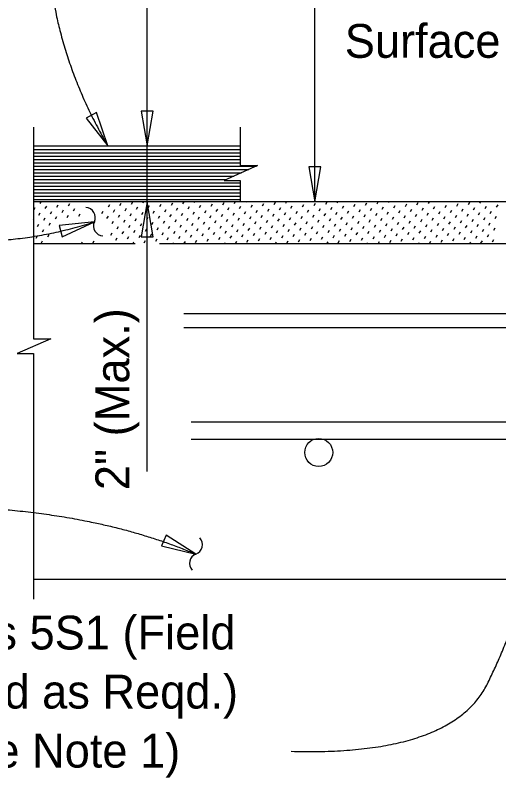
# Model space of a CAD drawing. Extents: x 120632.7 to 120668.8, y 120715.7 to 120740.6.
# Drawn here: x 120645.927 to 120647.369, y 120721.862 to 120724.135 of the extents above; entities that cross this region are included whole.
import ezdxf

# ---------------------------------------------------------------- set-up
doc = ezdxf.new("R2010")
doc.units = 0
for name, color, linetype in [('Dimension', 7, 'Continuous'), ('Miscellaneous', 7, 'Continuous'), ('Rebar_h', 7, 'Continuous'), ('TextStructures', 7, 'Continuous'), ('TrafBarrierConc', 7, 'Continuous')]:
    doc.layers.add(name, color=color, linetype=linetype)

msp = doc.modelspace()

# ---------------------------------------------------------------- linework, layer by layer
at = {"layer": 'Dimension'}
for p, q in [((120646.3205, 120722.7748), (120646.3205, 120726.2451)), ((120646.8205, 120723.5784), (120646.8205, 120726.2451))]:
    msp.add_line(p, q, dxfattribs=at)
for points in [[(120646.3205, 120723.7451), (120646.3382, 120723.8492), (120646.3029, 120723.8492)], [(120646.2035, 120723.7451), (120646.1695, 120723.845), (120646.1384, 120723.8282)], [(120646.8205, 120723.5784), (120646.8382, 120723.6826), (120646.8029, 120723.6826)], [(120646.3205, 120723.5784), (120646.3029, 120723.4743), (120646.3382, 120723.4743)], [(120646.1632, 120723.5191), (120646.0582, 120723.5084), (120646.0675, 120723.4744)], [(120646.4659, 120722.5283), (120646.3771, 120722.5855), (120646.3633, 120722.553)]]:
    msp.add_lwpolyline(points, close=True, dxfattribs=at)
for points in [[(120645.9811, 120723.8013), (120645.9811, 120723.1705), (120646.0328, 120723.1705), (120645.9328, 120723.1263), (120645.9811, 120723.1263), (120645.9811, 120722.3942)], [(120646.5983, 120723.8013), (120646.5983, 120723.6865), (120646.65, 120723.6865), (120646.55, 120723.6423), (120646.5983, 120723.6423), (120646.5983, 120723.5784)]]:
    msp.add_lwpolyline(points, dxfattribs=at)
for centre, start, end in [((120646.1361, 120723.5319), 335.1447, 86.8719), ((120646.1902, 120723.5069), 155.1447, 266.8719), ((120646.4554, 120722.5564), 291.0208, 42.748), ((120646.4768, 120722.5008), 111.0208, 222.748)]:
    msp.add_arc(centre, 0.0298, start, end, dxfattribs=at)
for points in [[(120645.8334, 120724.7826), (120646.0481, 120724.7906), (120646.0065, 120724.0831), (120646.2035, 120723.7451)], [(120645.7174, 120723.4648), (120645.9402, 120723.4472), (120646.1633, 120723.519)], [(120646.75, 120721.9408), (120647.2284, 120721.9277), (120647.4429, 120722.3562), (120647.6394, 120723.1429), (120647.8936, 120723.5), (120648.3041, 120723.1905)], [(120645.6303, 120722.6723), (120646.1265, 120722.6734), (120646.466, 120722.5283)]]:
    msp.add_open_spline(points, degree=2, dxfattribs=at)
at = {"layer": 'Miscellaneous'}
for p, q in [((120645.9812, 120723.7451), (120646.5984, 120723.7451)), ((120645.9812, 120723.7351), (120646.5984, 120723.7351)), ((120645.9812, 120723.7251), (120646.5984, 120723.7251)), ((120645.9812, 120723.7151), (120646.5984, 120723.7151)), ((120645.9812, 120723.7051), (120646.5984, 120723.7051)), ((120645.9812, 120723.6951), (120646.5984, 120723.6951)), ((120645.9812, 120723.6851), (120646.6469, 120723.6851)), ((120645.9812, 120723.6751), (120646.6243, 120723.6751)), ((120645.9812, 120723.6651), (120646.6016, 120723.6651)), ((120645.9812, 120723.6551), (120646.579, 120723.6551)), ((120645.9812, 120723.6451), (120646.5563, 120723.6451)), ((120645.9812, 120723.6351), (120646.5984, 120723.6351)), ((120645.9812, 120723.6251), (120646.5984, 120723.6251)), ((120645.9812, 120723.6151), (120646.5984, 120723.6151)), ((120645.9812, 120723.6051), (120646.5984, 120723.6051)), ((120645.9812, 120723.5951), (120646.5984, 120723.5951)), ((120645.9812, 120723.5851), (120646.5984, 120723.5851)), ((120647.6222, 120723.5784), (120645.9812, 120723.5784)), ((120646.0016, 120723.5738), (120646.0043, 120723.5784)), ((120646.0361, 120723.5778), (120646.0365, 120723.5784)), ((120646.2739, 120723.5716), (120646.2778, 120723.5784)), ((120646.3084, 120723.5757), (120646.31, 120723.5784)), ((120646.3928, 120723.5685), (120646.3968, 120723.5755)), ((120646.4273, 120723.5726), (120646.4307, 120723.5784)), ((120646.4619, 120723.5766), (120646.4629, 120723.5784)), ((120646.5462, 120723.5695), (120646.5503, 120723.5765)), ((120646.5808, 120723.5736), (120646.5836, 120723.5784)), ((120646.6153, 120723.5776), (120646.6158, 120723.5784)), ((120646.6996, 120723.5705), (120646.7037, 120723.5775)), ((120646.7342, 120723.5745), (120646.7364, 120723.5784)), ((120646.8531, 120723.5714), (120646.8571, 120723.5784)), ((120646.8876, 120723.5755), (120646.8893, 120723.5784)), ((120646.9719, 120723.5683), (120646.976, 120723.5753)), ((120647.0065, 120723.5724), (120647.01, 120723.5784)), ((120647.041, 120723.5764), (120647.0422, 120723.5784)), ((120647.1254, 120723.5693), (120647.1294, 120723.5763)), ((120647.1599, 120723.5733), (120647.1629, 120723.5784)), ((120647.1945, 120723.5774), (120647.1951, 120723.5784)), ((120647.2788, 120723.5702), (120647.2829, 120723.5772)), ((120647.3133, 120723.5743), (120647.3157, 120723.5784)), ((120647.3479, 120723.5783), (120647.3479, 120723.5784)), ((120645.9823, 120723.5545), (120645.9863, 120723.5615)), ((120646.0168, 120723.5585), (120646.0209, 120723.5655)), ((120646.0514, 120723.5626), (120646.0554, 120723.5696)), ((120646.0666, 120723.5473), (120646.0707, 120723.5543)), ((120646.0859, 120723.5666), (120646.09, 120723.5736)), ((120646.1012, 120723.5514), (120646.1052, 120723.5584)), ((120646.2048, 120723.5635), (120646.2089, 120723.5705)), ((120646.2201, 120723.5483), (120646.2241, 120723.5553)), ((120646.2394, 120723.5676), (120646.2434, 120723.5746)), ((120646.2546, 120723.5523), (120646.2587, 120723.5593)), ((120646.2891, 120723.5564), (120646.2932, 120723.5634)), ((120646.3237, 120723.5604), (120646.3277, 120723.5674)), ((120646.3389, 120723.5452), (120646.343, 120723.5522)), ((120646.3582, 120723.5645), (120646.3623, 120723.5715)), ((120646.3735, 120723.5492), (120646.3775, 120723.5562)), ((120646.408, 120723.5533), (120646.4121, 120723.5603)), ((120646.4426, 120723.5574), (120646.4466, 120723.5643)), ((120646.4771, 120723.5614), (120646.4812, 120723.5684)), ((120646.4924, 120723.5462), (120646.4964, 120723.5532)), ((120646.5117, 120723.5655), (120646.5157, 120723.5725)), ((120646.5269, 120723.5502), (120646.531, 120723.5572)), ((120646.5615, 120723.5543), (120646.5655, 120723.5613)), ((120646.596, 120723.5583), (120646.6001, 120723.5653)), ((120646.6305, 120723.5624), (120646.6346, 120723.5694)), ((120646.6458, 120723.5471), (120646.6498, 120723.5541)), ((120646.6651, 120723.5664), (120646.6691, 120723.5734)), ((120646.6803, 120723.5512), (120646.6844, 120723.5582)), ((120646.7149, 120723.5552), (120646.7189, 120723.5622)), ((120646.7494, 120723.5593), (120646.7535, 120723.5663)), ((120646.784, 120723.5633), (120646.788, 120723.5703)), ((120646.7992, 120723.5481), (120646.8033, 120723.5551)), ((120646.8185, 120723.5674), (120646.8226, 120723.5744)), ((120646.8338, 120723.5521), (120646.8378, 120723.5591)), ((120646.8683, 120723.5562), (120646.8724, 120723.5632)), ((120646.9029, 120723.5602), (120646.9069, 120723.5672)), ((120646.9181, 120723.545), (120646.9222, 120723.552)), ((120646.9374, 120723.5643), (120646.9415, 120723.5713)), ((120646.9527, 120723.549), (120646.9567, 120723.556)), ((120646.9872, 120723.5531), (120646.9912, 120723.5601)), ((120647.0217, 120723.5571), (120647.0258, 120723.5641)), ((120647.0563, 120723.5612), (120647.0603, 120723.5682)), ((120647.0715, 120723.5459), (120647.0756, 120723.5529)), ((120647.0908, 120723.5652), (120647.0949, 120723.5722)), ((120647.1061, 120723.55), (120647.1101, 120723.557)), ((120647.1406, 120723.554), (120647.1447, 120723.561)), ((120647.1752, 120723.5581), (120647.1792, 120723.5651)), ((120647.2097, 120723.5621), (120647.2138, 120723.5691)), ((120647.225, 120723.5469), (120647.229, 120723.5539)), ((120647.2443, 120723.5662), (120647.2483, 120723.5732)), ((120647.2595, 120723.5509), (120647.2636, 120723.5579)), ((120647.2941, 120723.555), (120647.2981, 120723.562)), ((120647.3286, 120723.559), (120647.3326, 120723.566)), ((120647.3631, 120723.5631), (120647.3672, 120723.5701)), ((120645.9975, 120723.5392), (120646.0016, 120723.5462)), ((120646.0128, 120723.524), (120646.0168, 120723.531)), ((120646.0321, 120723.5433), (120646.0361, 120723.5503)), ((120646.0473, 120723.528), (120646.0514, 120723.535)), ((120646.0819, 120723.5321), (120646.0859, 120723.5391)), ((120646.1164, 120723.5361), (120646.1205, 120723.5431)), ((120646.1855, 120723.5442), (120646.1896, 120723.5512)), ((120646.2008, 120723.529), (120646.2048, 120723.536)), ((120646.2353, 120723.533), (120646.2394, 120723.54)), ((120646.2699, 120723.5371), (120646.2739, 120723.5441)), ((120646.3044, 120723.5411), (120646.3084, 120723.5481)), ((120646.3196, 120723.5259), (120646.3237, 120723.5329)), ((120646.3542, 120723.5299), (120646.3582, 120723.5369)), ((120646.3887, 120723.534), (120646.3928, 120723.541)), ((120646.4233, 120723.5381), (120646.4273, 120723.545)), ((120646.4385, 120723.5228), (120646.4426, 120723.5298)), ((120646.4578, 120723.5421), (120646.4619, 120723.5491)), ((120646.4731, 120723.5269), (120646.4771, 120723.5339)), ((120646.5076, 120723.5309), (120646.5117, 120723.5379)), ((120646.5422, 120723.535), (120646.5462, 120723.542)), ((120646.5767, 120723.539), (120646.5808, 120723.546)), ((120646.592, 120723.5238), (120646.596, 120723.5308)), ((120646.6113, 120723.5431), (120646.6153, 120723.5501)), ((120646.6265, 120723.5278), (120646.6305, 120723.5348)), ((120646.661, 120723.5319), (120646.6651, 120723.5389)), ((120646.6956, 120723.5359), (120646.6996, 120723.5429)), ((120646.7301, 120723.54), (120646.7342, 120723.547)), ((120646.7454, 120723.5247), (120646.7494, 120723.5317)), ((120646.7647, 120723.544), (120646.7687, 120723.551)), ((120646.7799, 120723.5288), (120646.784, 120723.5358)), ((120646.8145, 120723.5328), (120646.8185, 120723.5398)), ((120646.849, 120723.5369), (120646.8531, 120723.5439)), ((120646.8836, 120723.5409), (120646.8876, 120723.5479)), ((120646.8988, 120723.5257), (120646.9029, 120723.5327)), ((120646.9334, 120723.5297), (120646.9374, 120723.5367)), ((120646.9679, 120723.5338), (120646.9719, 120723.5408)), ((120647.0024, 120723.5378), (120647.0065, 120723.5448)), ((120647.0177, 120723.5226), (120647.0217, 120723.5296)), ((120647.037, 120723.5419), (120647.041, 120723.5489)), ((120647.0522, 120723.5266), (120647.0563, 120723.5336)), ((120647.0868, 120723.5307), (120647.0908, 120723.5377)), ((120647.1213, 120723.5347), (120647.1254, 120723.5417)), ((120647.1559, 120723.5388), (120647.1599, 120723.5458)), ((120647.1711, 120723.5235), (120647.1752, 120723.5305)), ((120647.1904, 120723.5428), (120647.1945, 120723.5498)), ((120647.2057, 120723.5276), (120647.2097, 120723.5346)), ((120647.2402, 120723.5316), (120647.2443, 120723.5386)), ((120647.2748, 120723.5357), (120647.2788, 120723.5427)), ((120647.3093, 120723.5397), (120647.3133, 120723.5467)), ((120647.3245, 120723.5245), (120647.3286, 120723.5315)), ((120647.3438, 120723.5438), (120647.3479, 120723.5508)), ((120647.3591, 120723.5286), (120647.3631, 120723.5355)), ((120645.9812, 120723.5251), (120645.9823, 120723.5269)), ((120645.9935, 120723.5047), (120645.9975, 120723.5117)), ((120646.028, 120723.5087), (120646.0321, 120723.5157)), ((120646.216, 120723.5137), (120646.2201, 120723.5207)), ((120646.2506, 120723.5178), (120646.2546, 120723.5248)), ((120646.2658, 120723.5025), (120646.2699, 120723.5095)), ((120646.2851, 120723.5218), (120646.2891, 120723.5288)), ((120646.3003, 120723.5066), (120646.3044, 120723.5136)), ((120646.3349, 120723.5107), (120646.3389, 120723.5176)), ((120646.3694, 120723.5147), (120646.3735, 120723.5217)), ((120646.404, 120723.5188), (120646.408, 120723.5258)), ((120646.4192, 120723.5035), (120646.4233, 120723.5105)), ((120646.4538, 120723.5076), (120646.4578, 120723.5146)), ((120646.4883, 120723.5116), (120646.4924, 120723.5186)), ((120646.5229, 120723.5157), (120646.5269, 120723.5227)), ((120646.5381, 120723.5004), (120646.5422, 120723.5074)), ((120646.5574, 120723.5197), (120646.5615, 120723.5267)), ((120646.5727, 120723.5045), (120646.5767, 120723.5115)), ((120646.6072, 120723.5085), (120646.6113, 120723.5155)), ((120646.6417, 120723.5126), (120646.6458, 120723.5196)), ((120646.6763, 120723.5166), (120646.6803, 120723.5236)), ((120646.6915, 120723.5014), (120646.6956, 120723.5084)), ((120646.7108, 120723.5207), (120646.7149, 120723.5277)), ((120646.7261, 120723.5054), (120646.7301, 120723.5124)), ((120646.7606, 120723.5095), (120646.7647, 120723.5165)), ((120646.7952, 120723.5135), (120646.7992, 120723.5205)), ((120646.8297, 120723.5176), (120646.8338, 120723.5246)), ((120646.845, 120723.5023), (120646.849, 120723.5093)), ((120646.8643, 120723.5216), (120646.8683, 120723.5286)), ((120646.8795, 120723.5064), (120646.8836, 120723.5134)), ((120646.9141, 120723.5104), (120646.9181, 120723.5174)), ((120646.9486, 120723.5145), (120646.9527, 120723.5215)), ((120646.9831, 120723.5185), (120646.9872, 120723.5255)), ((120646.9984, 120723.5033), (120647.0024, 120723.5103)), ((120647.0329, 120723.5073), (120647.037, 120723.5143)), ((120647.0675, 120723.5114), (120647.0715, 120723.5184)), ((120647.102, 120723.5154), (120647.1061, 120723.5224)), ((120647.1173, 120723.5002), (120647.1213, 120723.5072)), ((120647.1366, 120723.5195), (120647.1406, 120723.5265)), ((120647.1518, 120723.5042), (120647.1559, 120723.5112)), ((120647.1864, 120723.5083), (120647.1904, 120723.5153)), ((120647.2209, 120723.5123), (120647.225, 120723.5193)), ((120647.2555, 120723.5164), (120647.2595, 120723.5234)), ((120647.2707, 120723.5012), (120647.2748, 120723.5081)), ((120647.29, 120723.5204), (120647.2941, 120723.5274)), ((120647.3052, 120723.5052), (120647.3093, 120723.5122)), ((120647.3398, 120723.5093), (120647.3438, 120723.5162)), ((120646.0087, 120723.4894), (120646.0128, 120723.4964)), ((120646.212, 120723.4792), (120646.216, 120723.4862)), ((120646.2313, 120723.4985), (120646.2353, 120723.5055)), ((120646.2465, 120723.4833), (120646.2506, 120723.4902)), ((120646.281, 120723.4873), (120646.2851, 120723.4943)), ((120646.3156, 120723.4914), (120646.3196, 120723.4984)), ((120646.3501, 120723.4954), (120646.3542, 120723.5024)), ((120646.3654, 120723.4802), (120646.3694, 120723.4872)), ((120646.3847, 120723.4995), (120646.3887, 120723.5065)), ((120646.3999, 120723.4842), (120646.404, 120723.4912)), ((120646.4345, 120723.4883), (120646.4385, 120723.4953)), ((120646.469, 120723.4923), (120646.4731, 120723.4993)), ((120646.4843, 120723.4771), (120646.4883, 120723.4841)), ((120646.5036, 120723.4964), (120646.5076, 120723.5034)), ((120646.5188, 120723.4811), (120646.5229, 120723.4881)), ((120646.5534, 120723.4852), (120646.5574, 120723.4922)), ((120646.5879, 120723.4892), (120646.592, 120723.4962)), ((120646.6224, 120723.4933), (120646.6265, 120723.5003)), ((120646.6377, 120723.478), (120646.6417, 120723.485)), ((120646.657, 120723.4973), (120646.661, 120723.5043)), ((120646.6722, 120723.4821), (120646.6763, 120723.4891)), ((120646.7068, 120723.4861), (120646.7108, 120723.4931)), ((120646.7413, 120723.4902), (120646.7454, 120723.4972)), ((120646.7759, 120723.4942), (120646.7799, 120723.5012)), ((120646.7911, 120723.479), (120646.7952, 120723.486)), ((120646.8104, 120723.4983), (120646.8145, 120723.5053)), ((120646.8257, 120723.483), (120646.8297, 120723.49)), ((120646.8602, 120723.4871), (120646.8643, 120723.4941)), ((120646.8948, 120723.4911), (120646.8988, 120723.4981)), ((120646.9293, 120723.4952), (120646.9334, 120723.5022)), ((120646.9445, 120723.4799), (120646.9486, 120723.4869)), ((120646.9638, 120723.4992), (120646.9679, 120723.5062)), ((120646.9791, 120723.484), (120646.9831, 120723.491)), ((120647.0136, 120723.488), (120647.0177, 120723.495)), ((120647.0482, 120723.4921), (120647.0522, 120723.4991)), ((120647.0634, 120723.4768), (120647.0675, 120723.4838)), ((120647.0827, 120723.4961), (120647.0868, 120723.5031)), ((120647.098, 120723.4809), (120647.102, 120723.4879)), ((120647.1325, 120723.4849), (120647.1366, 120723.4919)), ((120647.1671, 120723.489), (120647.1711, 120723.496)), ((120647.2016, 120723.493), (120647.2057, 120723.5)), ((120647.2169, 120723.4778), (120647.2209, 120723.4848)), ((120647.2362, 120723.4971), (120647.2402, 120723.5041)), ((120647.2514, 120723.4819), (120647.2555, 120723.4888)), ((120647.2859, 120723.4859), (120647.29, 120723.4929)), ((120647.3205, 120723.49), (120647.3245, 120723.497)), ((120647.355, 120723.494), (120647.3591, 120723.501)), ((120645.9894, 120723.4701), (120645.9935, 120723.4771)), ((120646.0047, 120723.4549), (120646.0087, 120723.4619)), ((120646.024, 120723.4742), (120646.028, 120723.4812)), ((120646.1581, 120723.4559), (120646.1622, 120723.4628)), ((120646.2272, 120723.464), (120646.2313, 120723.471)), ((120646.2617, 120723.468), (120646.2658, 120723.475)), ((120646.2963, 120723.4721), (120646.3003, 120723.4791)), ((120646.3115, 120723.4568), (120646.3156, 120723.4638)), ((120646.3308, 120723.4761), (120646.3349, 120723.4831)), ((120646.3461, 120723.4609), (120646.3501, 120723.4679)), ((120646.3806, 120723.4649), (120646.3847, 120723.4719)), ((120646.4152, 120723.469), (120646.4192, 120723.476)), ((120646.4497, 120723.473), (120646.4538, 120723.48)), ((120646.465, 120723.4578), (120646.469, 120723.4648)), ((120646.4995, 120723.4618), (120646.5036, 120723.4688)), ((120646.5341, 120723.4659), (120646.5381, 120723.4729)), ((120646.5686, 120723.4699), (120646.5727, 120723.4769)), ((120646.5839, 120723.4547), (120646.5879, 120723.4617)), ((120646.6031, 120723.474), (120646.6072, 120723.481)), ((120646.6184, 120723.4587), (120646.6224, 120723.4657)), ((120646.6529, 120723.4628), (120646.657, 120723.4698)), ((120646.6875, 120723.4668), (120646.6915, 120723.4738)), ((120646.722, 120723.4709), (120646.7261, 120723.4779)), ((120646.7373, 120723.4556), (120646.7413, 120723.4626)), ((120646.7566, 120723.4749), (120646.7606, 120723.4819)), ((120646.7718, 120723.4597), (120646.7759, 120723.4667)), ((120646.8064, 120723.4637), (120646.8104, 120723.4707)), ((120646.8409, 120723.4678), (120646.845, 120723.4748)), ((120646.8755, 120723.4718), (120646.8795, 120723.4788)), ((120646.8907, 120723.4566), (120646.8948, 120723.4636)), ((120646.91, 120723.4759), (120646.9141, 120723.4829)), ((120646.9253, 120723.4606), (120646.9293, 120723.4676)), ((120646.9598, 120723.4647), (120646.9638, 120723.4717)), ((120646.9943, 120723.4687), (120646.9984, 120723.4757)), ((120647.0289, 120723.4728), (120647.0329, 120723.4798)), ((120647.0441, 120723.4575), (120647.0482, 120723.4645)), ((120647.0787, 120723.4616), (120647.0827, 120723.4686)), ((120647.1132, 120723.4656), (120647.1173, 120723.4726)), ((120647.1478, 120723.4697), (120647.1518, 120723.4767)), ((120647.163, 120723.4545), (120647.1671, 120723.4614)), ((120647.1823, 120723.4737), (120647.1864, 120723.4807)), ((120647.1976, 120723.4585), (120647.2016, 120723.4655)), ((120647.2321, 120723.4626), (120647.2362, 120723.4696)), ((120647.2667, 120723.4666), (120647.2707, 120723.4736)), ((120647.3012, 120723.4707), (120647.3052, 120723.4777)), ((120647.3164, 120723.4554), (120647.3205, 120723.4624)), ((120647.3357, 120723.4747), (120647.3398, 120723.4817)), ((120647.351, 120723.4595), (120647.355, 120723.4665)), ((120646.0923, 120723.4534), (120646.0931, 120723.4547)), ((120646.1245, 120723.4534), (120646.1276, 120723.4588)), ((120646.2452, 120723.4534), (120646.2465, 120723.4557)), ((120646.2774, 120723.4534), (120646.281, 120723.4598)), ((120646.398, 120723.4534), (120646.3999, 120723.4567)), ((120646.4304, 120723.4537), (120646.4345, 120723.4607)), ((120646.5187, 120723.4534), (120646.5188, 120723.4536)), ((120646.5509, 120723.4534), (120646.5534, 120723.4576)), ((120646.6716, 120723.4534), (120646.6722, 120723.4545)), ((120646.7038, 120723.4534), (120646.7068, 120723.4586)), ((120646.8245, 120723.4534), (120646.8257, 120723.4555)), ((120646.8567, 120723.4534), (120646.8602, 120723.4595)), ((120646.9773, 120723.4534), (120646.9791, 120723.4564)), ((120647.0096, 120723.4535), (120647.0136, 120723.4605)), ((120647.1302, 120723.4534), (120647.1325, 120723.4574)), ((120647.2509, 120723.4534), (120647.2514, 120723.4543)), ((120647.2831, 120723.4534), (120647.2859, 120723.4584))]:
    msp.add_line(p, q, dxfattribs=at)
at = {"layer": 'Rebar_h'}
for p, q in [((120647.8906, 120723.2451), (120646.4298, 120723.2451)), ((120647.8906, 120723.2034), (120646.4298, 120723.2034)), ((120648.6656, 120722.9221), (120646.4515, 120722.9221)), ((120648.6656, 120722.8701), (120646.4515, 120722.8701))]:
    msp.add_line(p, q, dxfattribs=at)
msp.add_circle((120646.8325, 120722.8315), 0.0417, dxfattribs=at)
at = {"layer": 'TrafBarrierConc'}
for p, q in [((120646.2844, 120723.4534), (120645.9812, 120723.4534)), ((120647.6222, 120723.4534), (120646.3578, 120723.4534)), ((120648.8323, 120722.4534), (120645.9811, 120722.4534))]:
    msp.add_line(p, q, dxfattribs=at)

# ---------------------------------------------------------------- texts
at = {"layer": 'Dimension'}
for s, p in [('Surface', (120646.9101, 120724.0079)), ('Bars 5S1 (Field', (120645.6551, 120722.2443)), ('Bend as Reqd.)', (120645.6551, 120722.0683)), ('(See Note 1)', (120645.6551, 120721.8923))]:
    msp.add_text(s, height=0.1008, dxfattribs=at).set_placement(p)
at = {"layer": 'TextStructures'}
msp.add_text('2" (Max.)', height=0.1008, rotation=90, dxfattribs=at).set_placement((120646.2671, 120722.7193))

doc.saveas('drawing.dxf')
